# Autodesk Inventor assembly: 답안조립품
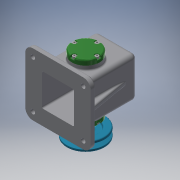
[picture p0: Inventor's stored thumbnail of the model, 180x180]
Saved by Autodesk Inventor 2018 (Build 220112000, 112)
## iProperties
Created: 2022-11
Part Number: 답안조립품
Material: 일반
Document SubType Name: Assembly
Designer: home
Author: home
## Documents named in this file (11)
- C:\Users\kimgi\Desktop\721106V1006\답안조립품.iam
- C:\Users\kimgi\Desktop\721106V1006\본체.ipt
- C:\Users\kimgi\Desktop\721106V1006\앞커버.ipt
- C:\Users\kimgi\Desktop\721106V1006\뒤커버.ipt
- C:\Users\kimgi\Desktop\721106V1006\베어링 6201.ipt
- C:\Users\kimgi\Desktop\721106V1006\편심축.ipt
- C:\Users\kimgi\Desktop\721106V1006\오일실 12 25 7.ipt
- C:\Users\kimgi\Desktop\721106V1006\V벨트풀리.ipt
- C:\Users\kimgi\Desktop\721106V1006\키 4 x 4 x 15.ipt
- C:\Users\kimgi\Desktop\721106V1006\멈춤나사 M3 x 8.ipt
- C:\Users\kimgi\Desktop\721106V1006\볼트 M4 x 12.ipt
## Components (9 placed, 2 different names)
1. V벨트풀리:1 — 각도:2
2. ISO 4762 M4 x 12:1
3. ISO 4762 M4 x 12:2
4. ISO 4762 M4 x 12:3
5. ISO 4762 M4 x 12:4
6. ISO 4762 M4 x 12:5
7. ISO 4762 M4 x 12:6
8. ISO 4762 M4 x 12:7
9. ISO 4762 M4 x 12:8
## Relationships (1: Angle 1)
- 각도:2 [Angle]: V벨트풀리:1
